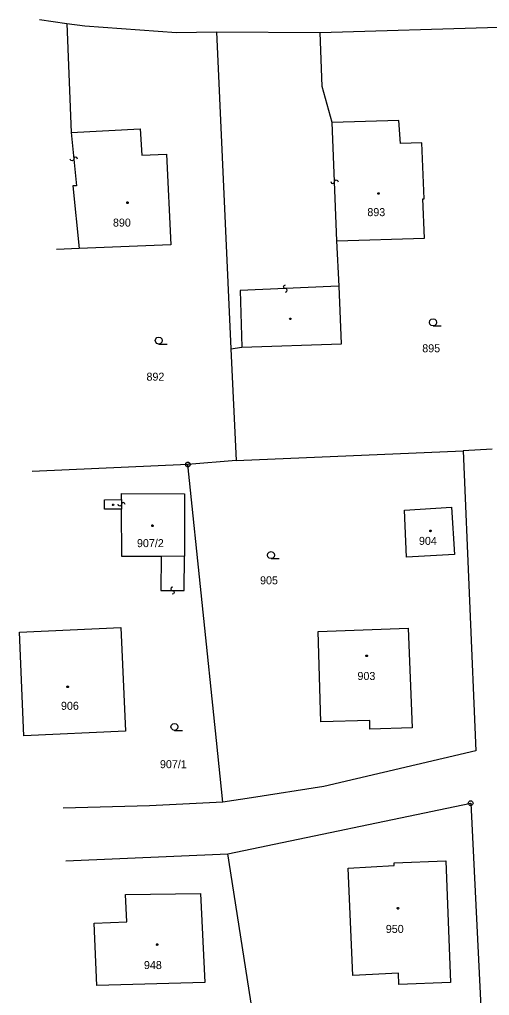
# Model space of a CAD drawing. Extents: x -456675 to -456278, y -1112395 to -1112217.
# Drawn here: x -456675.4 to -456625.5, y -1112328.7 to -1112225.1 of the extents above; entities that cross this region are included whole.
import ezdxf

# ---------------------------------------------------------------- set-up
doc = ezdxf.new("R2010")
doc.units = 0
doc.layers.add('Katastralni_mapa', color=7, linetype='Continuous')

msp = doc.modelspace()

# ---------------------------------------------------------------- linework, layer by layer
at = {"layer": 'Katastralni_mapa'}
for points in [[(-456673.23, -1112225.05), (-456670.33, -1112225.46)], [(-456670.33, -1112225.46), (-456668.4, -1112225.73)], [(-456670.33, -1112225.46), (-456669.85, -1112237.05)], [(-456668.4, -1112225.73), (-456658.7, -1112226.44)], [(-456658.7, -1112226.44), (-456654.45, -1112226.37)], [(-456654.45, -1112226.37), (-456652.9, -1112260.04)], [(-456654.45, -1112226.37), (-456643.44, -1112226.42)], [(-456643.44, -1112226.42), (-456624.5, -1112225.87)], [(-456643.23, -1112232.16), (-456643.44, -1112226.42)], [(-456642.16, -1112236), (-456643.23, -1112232.16)], [(-456635.07, -1112235.77), (-456642.16, -1112236)], [(-456634.91, -1112238.22), (-456635.07, -1112235.77)], [(-456669.85, -1112237.05), (-456662.53, -1112236.67)], [(-456662.53, -1112236.67), (-456662.38, -1112239.45)], [(-456641.66, -1112248.56), (-456642.16, -1112236)], [(-456669.85, -1112237.05), (-456669.31, -1112242.71)], [(-456632.64, -1112238.16), (-456634.91, -1112238.22)], [(-456632.4, -1112244.1), (-456632.64, -1112238.16)], [(-456669.2, -1112239.87), (-456669.27, -1112239.72), (-456669.43, -1112239.68), (-456669.56, -1112239.76), (-456669.62, -1112240.01), (-456669.75, -1112240.08), (-456669.9, -1112240.03), (-456669.96, -1112239.89)], [(-456662.38, -1112239.45), (-456659.74, -1112239.34)], [(-456659.74, -1112239.34), (-456659.27, -1112248.98)], [(-456669.31, -1112242.71), (-456669.68, -1112242.72)], [(-456669.68, -1112242.72), (-456669.02, -1112249.36)], [(-456642.29, -1112242.27), (-456642.23, -1112242.42), (-456642.07, -1112242.47), (-456641.94, -1112242.4), (-456641.87, -1112242.15), (-456641.73, -1112242.09), (-456641.58, -1112242.15), (-456641.53, -1112242.29)], [(-456632.37, -1112248.27), (-456632.53, -1112244.1)], [(-456632.53, -1112244.1), (-456632.4, -1112244.1)], [(-456659.27, -1112248.98), (-456669.02, -1112249.36)], [(-456641.66, -1112248.56), (-456632.37, -1112248.27)], [(-456641.43, -1112253.37), (-456641.66, -1112248.56)], [(-456669.02, -1112249.36), (-456671.43, -1112249.49)], [(-456642.29, -1112253.41), (-456651.94, -1112253.85)], [(-456647.12, -1112254.01), (-456646.98, -1112253.95), (-456646.92, -1112253.79), (-456647, -1112253.66), (-456647.24, -1112253.59), (-456647.31, -1112253.45), (-456647.25, -1112253.3), (-456647.11, -1112253.25)], [(-456641.43, -1112253.37), (-456642.29, -1112253.41)], [(-456641.15, -1112259.51), (-456641.43, -1112253.37)], [(-456651.94, -1112253.85), (-456651.73, -1112259.87)], [(-456631.45, -1112257.59), (-456631.64, -1112257.54), (-456631.77, -1112257.4), (-456631.82, -1112257.22), (-456631.77, -1112257.03), (-456631.64, -1112256.89), (-456631.45, -1112256.84), (-456631.26, -1112256.89), (-456631.12, -1112257.03), (-456631.07, -1112257.22), (-456631.12, -1112257.4), (-456631.26, -1112257.54), (-456631.45, -1112257.59), (-456630.57, -1112257.59)], [(-456660.57, -1112259.53), (-456660.76, -1112259.48), (-456660.89, -1112259.34), (-456660.94, -1112259.15), (-456660.89, -1112258.97), (-456660.76, -1112258.83), (-456660.57, -1112258.78), (-456660.38, -1112258.83), (-456660.24, -1112258.97), (-456660.19, -1112259.15), (-456660.24, -1112259.34), (-456660.38, -1112259.48), (-456660.57, -1112259.53), (-456659.69, -1112259.53)], [(-456651.73, -1112259.87), (-456641.15, -1112259.51)], [(-456652.9, -1112260.04), (-456651.73, -1112259.87)], [(-456652.9, -1112260.04), (-456652.35, -1112271.88)], [(-456652.35, -1112271.88), (-456628.25, -1112270.88)], [(-456625.18, -1112270.69), (-456628.25, -1112270.88)], [(-456628.25, -1112270.88), (-456626.9, -1112302.72)], [(-456652.35, -1112271.88), (-456657.48, -1112272.32)], [(-456657.48, -1112272.32), (-456674, -1112273.07)], [(-456657.51, -1112272.32), (-456657.45, -1112272.32)], [(-456654.45, -1112301.64), (-456657.48, -1112272.32)], [(-456664.51, -1112277.07), (-456666.34, -1112277.08), (-456666.32, -1112276.06), (-456664.52, -1112276.05)], [(-456664.52, -1112275.41), (-456657.82, -1112275.45), (-456657.82, -1112282.07)], [(-456664.52, -1112276.05), (-456664.52, -1112275.41)], [(-456664.52, -1112276.05), (-456664.51, -1112277.07)], [(-456664.14, -1112276.58), (-456664.19, -1112276.43), (-456664.35, -1112276.37), (-456664.48, -1112276.44), (-456664.56, -1112276.69), (-456664.7, -1112276.75), (-456664.85, -1112276.68), (-456664.89, -1112276.54)], [(-456660.32, -1112282.08), (-456664.49, -1112282.09), (-456664.51, -1112277.07)], [(-456634.49, -1112277.16), (-456629.5, -1112276.85)], [(-456634.28, -1112282.15), (-456634.49, -1112277.16)], [(-456629.5, -1112276.85), (-456629.18, -1112281.88)], [(-456660.32, -1112282.08), (-456660.36, -1112285.72), (-456657.86, -1112285.72), (-456657.82, -1112282.07)], [(-456657.82, -1112282.07), (-456660.32, -1112282.08)], [(-456648.65, -1112282.32), (-456648.84, -1112282.27), (-456648.97, -1112282.13), (-456649.02, -1112281.94), (-456648.97, -1112281.76), (-456648.84, -1112281.62), (-456648.65, -1112281.57), (-456648.46, -1112281.62), (-456648.32, -1112281.76), (-456648.27, -1112281.94), (-456648.32, -1112282.13), (-456648.46, -1112282.27), (-456648.65, -1112282.32), (-456647.77, -1112282.32)], [(-456629.18, -1112281.88), (-456634.28, -1112282.15)], [(-456659.09, -1112285.34), (-456659.24, -1112285.4), (-456659.3, -1112285.55), (-456659.23, -1112285.69), (-456658.98, -1112285.77), (-456658.92, -1112285.91), (-456658.99, -1112286.05), (-456659.13, -1112286.1)], [(-456675.35, -1112290.13), (-456664.59, -1112289.65)], [(-456664.59, -1112289.65), (-456664.1, -1112300.64)], [(-456674.89, -1112301.14), (-456675.35, -1112290.13)], [(-456643.66, -1112290.06), (-456634.08, -1112289.72)], [(-456643.35, -1112299.66), (-456643.66, -1112290.06)], [(-456634.08, -1112289.72), (-456633.65, -1112300.29)], [(-456658.9, -1112300.57), (-456659.09, -1112300.52), (-456659.23, -1112300.38), (-456659.28, -1112300.2), (-456659.23, -1112300.01), (-456659.09, -1112299.87), (-456658.9, -1112299.82), (-456658.71, -1112299.87), (-456658.58, -1112300.01), (-456658.53, -1112300.2), (-456658.58, -1112300.38), (-456658.71, -1112300.52), (-456658.9, -1112300.57), (-456658.03, -1112300.57)], [(-456638.17, -1112299.5), (-456643.35, -1112299.66)], [(-456638.15, -1112300.45), (-456638.17, -1112299.5)], [(-456664.1, -1112300.64), (-456674.89, -1112301.14)], [(-456633.65, -1112300.29), (-456638.15, -1112300.45)], [(-456653.78, -1112308.19), (-456654.45, -1112301.64)], [(-456626.9, -1112302.72), (-456643.05, -1112306.53)], [(-456643.05, -1112306.53), (-456650.71, -1112307.72)], [(-456653.78, -1112308.19), (-456661.56, -1112308.57)], [(-456650.71, -1112307.72), (-456653.78, -1112308.19)], [(-456653.24, -1112313.68), (-456627.45, -1112308.3)], [(-456627.48, -1112308.3), (-456627.43, -1112308.3)], [(-456627.45, -1112308.3), (-456625.73, -1112342.97)], [(-456661.56, -1112308.57), (-456670.7, -1112308.84)], [(-456670.44, -1112314.43), (-456653.24, -1112313.68)], [(-456648.52, -1112343.82), (-456653.24, -1112313.68)], [(-456635.59, -1112314.64), (-456630.09, -1112314.41)], [(-456630.09, -1112314.41), (-456629.6, -1112327.34)], [(-456640.44, -1112315.19), (-456635.59, -1112314.92)], [(-456639.95, -1112326.61), (-456640.44, -1112315.19)], [(-456635.59, -1112314.92), (-456635.59, -1112314.64)], [(-456664.09, -1112318.01), (-456656.12, -1112317.88)], [(-456663.97, -1112320.91), (-456664.09, -1112318.01)], [(-456656.12, -1112317.88), (-456655.66, -1112327.35)], [(-456667.41, -1112321.04), (-456663.97, -1112320.91)], [(-456667.13, -1112327.67), (-456667.41, -1112321.04)], [(-456635.11, -1112326.37), (-456639.95, -1112326.61)], [(-456635.07, -1112327.55), (-456635.11, -1112326.37)], [(-456655.66, -1112327.35), (-456667.13, -1112327.67)], [(-456629.6, -1112327.34), (-456635.07, -1112327.55)]]:
    msp.add_lwpolyline(points, dxfattribs=at)
for points in [[(-456637.22, -1112243.45), (-456637.17, -1112243.46), (-456637.15, -1112243.5), (-456637.14, -1112243.53), (-456637.15, -1112243.58), (-456637.19, -1112243.61), (-456637.22, -1112243.62), (-456637.27, -1112243.6), (-456637.3, -1112243.57), (-456637.31, -1112243.53), (-456637.3, -1112243.49), (-456637.26, -1112243.45)], [(-456663.88, -1112244.43), (-456663.83, -1112244.44), (-456663.81, -1112244.48), (-456663.8, -1112244.51), (-456663.81, -1112244.56), (-456663.85, -1112244.59), (-456663.88, -1112244.6), (-456663.93, -1112244.58), (-456663.96, -1112244.55), (-456663.97, -1112244.51), (-456663.96, -1112244.47), (-456663.92, -1112244.43)], [(-456646.56, -1112256.77), (-456646.52, -1112256.84), (-456646.56, -1112256.92), (-456646.66, -1112256.92), (-456646.7, -1112256.84), (-456646.66, -1112256.77)], [(-456657.4, -1112272.08), (-456657.28, -1112272.18), (-456657.23, -1112272.32), (-456657.28, -1112272.47), (-456657.4, -1112272.56), (-456657.55, -1112272.56), (-456657.68, -1112272.47), (-456657.73, -1112272.32), (-456657.68, -1112272.18), (-456657.55, -1112272.08)], [(-456665.38, -1112276.54), (-456665.33, -1112276.61), (-456665.38, -1112276.69), (-456665.46, -1112276.69), (-456665.51, -1112276.61), (-456665.46, -1112276.54)], [(-456661.23, -1112278.74), (-456661.18, -1112278.75), (-456661.15, -1112278.79), (-456661.15, -1112278.82), (-456661.15, -1112278.87), (-456661.19, -1112278.9), (-456661.23, -1112278.91), (-456661.28, -1112278.89), (-456661.3, -1112278.86), (-456661.31, -1112278.82), (-456661.3, -1112278.78), (-456661.27, -1112278.74)], [(-456631.72, -1112279.29), (-456631.67, -1112279.3), (-456631.64, -1112279.34), (-456631.64, -1112279.37), (-456631.64, -1112279.42), (-456631.68, -1112279.45), (-456631.72, -1112279.46), (-456631.77, -1112279.44), (-456631.8, -1112279.41), (-456631.8, -1112279.37), (-456631.8, -1112279.33), (-456631.76, -1112279.29)], [(-456638.49, -1112292.56), (-456638.44, -1112292.57), (-456638.42, -1112292.62), (-456638.41, -1112292.65), (-456638.42, -1112292.69), (-456638.45, -1112292.73), (-456638.49, -1112292.73), (-456638.54, -1112292.72), (-456638.57, -1112292.69), (-456638.57, -1112292.65), (-456638.57, -1112292.6), (-456638.53, -1112292.57)], [(-456670.24, -1112295.85), (-456670.19, -1112295.86), (-456670.16, -1112295.91), (-456670.15, -1112295.94), (-456670.16, -1112295.98), (-456670.2, -1112296.02), (-456670.24, -1112296.02), (-456670.28, -1112296.01), (-456670.31, -1112295.98), (-456670.32, -1112295.94), (-456670.31, -1112295.89), (-456670.27, -1112295.86)], [(-456627.38, -1112308.06), (-456627.25, -1112308.16), (-456627.2, -1112308.3), (-456627.25, -1112308.45), (-456627.38, -1112308.54), (-456627.53, -1112308.54), (-456627.65, -1112308.45), (-456627.7, -1112308.3), (-456627.65, -1112308.16), (-456627.53, -1112308.06)], [(-456635.17, -1112319.38), (-456635.12, -1112319.39), (-456635.1, -1112319.43), (-456635.08, -1112319.46), (-456635.1, -1112319.51), (-456635.14, -1112319.54), (-456635.17, -1112319.55), (-456635.21, -1112319.53), (-456635.24, -1112319.5), (-456635.26, -1112319.46), (-456635.24, -1112319.42), (-456635.2, -1112319.38)], [(-456660.75, -1112323.23), (-456660.7, -1112323.24), (-456660.67, -1112323.29), (-456660.66, -1112323.32), (-456660.67, -1112323.36), (-456660.71, -1112323.4), (-456660.75, -1112323.4), (-456660.79, -1112323.39), (-456660.82, -1112323.36), (-456660.83, -1112323.32), (-456660.82, -1112323.27), (-456660.78, -1112323.24)]]:
    msp.add_lwpolyline(points, close=True, dxfattribs=at)

# ---------------------------------------------------------------- texts
for s, p in [('893', (-456638.42, -1112245.94)), ('890', (-456665.43, -1112247.05)), ('895', (-456632.59, -1112260.4)), ('892', (-456661.87, -1112263.42)), ('907/2', (-456662.88, -1112281.1)), ('904', (-456632.94, -1112280.86)), ('905', (-456649.81, -1112285.05)), ('903', (-456639.47, -1112295.21)), ('906', (-456670.95, -1112298.38)), ('907/1', (-456660.44, -1112304.58)), ('950', (-456636.46, -1112322.08)), ('948', (-456662.14, -1112325.92))]:
    msp.add_text(s, height=0.85, dxfattribs=at).set_placement(p)

doc.saveas('drawing.dxf')
